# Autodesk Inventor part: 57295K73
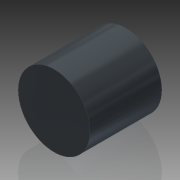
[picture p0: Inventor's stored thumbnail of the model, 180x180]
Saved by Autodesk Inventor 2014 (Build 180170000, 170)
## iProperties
Created: 2015-07
Part Number: 57295K73
Material: Iron, Gray
Document SubType Name: Modeling
Designer: Brad Factor
Density: 7.15 g/cm^3
Appearance: Iron Gray
Author: Brad Factor
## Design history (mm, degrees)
sketch "Sketch1"
  geometry: C1 r 3.175 at (0, 0); 1 further point
  constraints: 1 centre point, 1 coincident
  dimensions: "d0" = 6.35 diameter of C1
extrude "Extrusion1" new body sketch "Sketch1" stored distance "d1" = 6.35; taper "d2" = 0 deg
body "Solid1"
